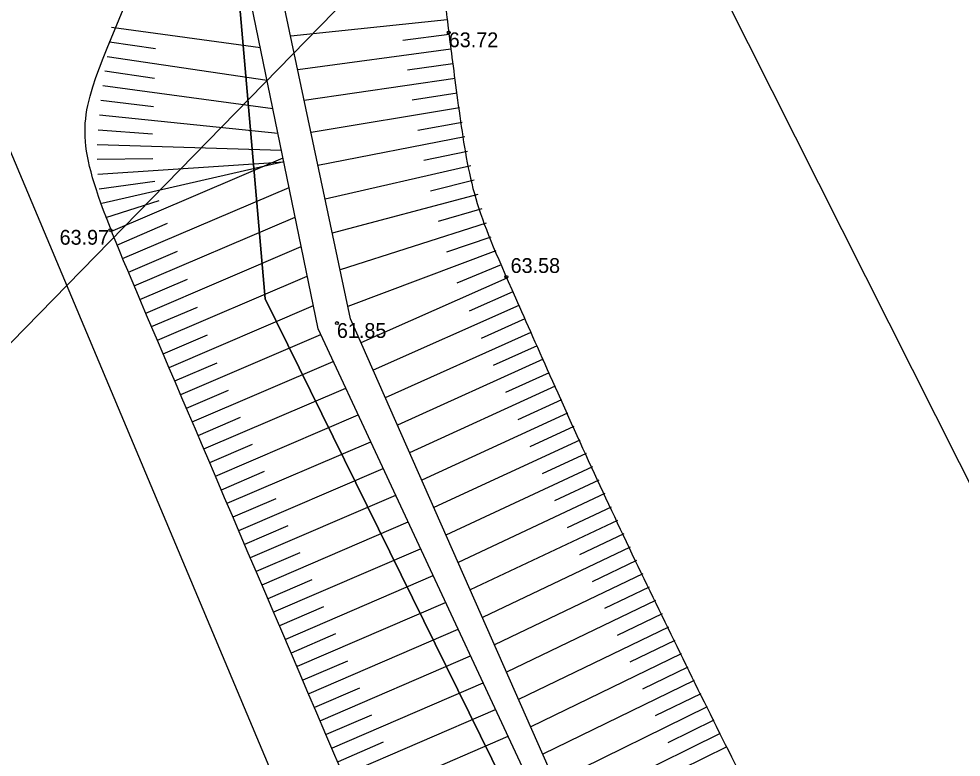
# Model space of a CAD drawing. Extents: x 616607 to 617499, y 408385 to 409695.
# Drawn here: x 617141.81 to 617173.68, y 409214.63 to 409239.59 of the extents above; entities that cross this region are included whole.
import ezdxf

# ---------------------------------------------------------------- set-up
doc = ezdxf.new("R2010")
doc.units = 0
for name, color, linetype in [('HIDG_GRAV_####_####_#', 7, 'Continuous'), ('RAMI_PLAN_####_TKST_#', 7, 'Continuous'), ('RAMI_UZMR_####_####_#', 7, 'Continuous'), ('RELJ_AATZ_####_TKST_#', 7, 'Continuous'), ('RELJ_ELEM_####_####_#', 7, 'Continuous'), ('RELJ_NOGA_####_####_#', 7, 'Continuous'), ('ROBZ_IERR_####_####_#', 7, 'Continuous'), ('ROBZ_UZMR_####_####_#', 7, 'Continuous')]:
    doc.layers.add(name, color=color, linetype=linetype)

# ---------------------------------------------------------------- blocks, each defined once
blk = doc.blocks.new('PKT')
at = {"layer": 'RELJ_ELEM_####_####_#'}
blk.add_circle((0, 0), 0.05, dxfattribs=at)

msp = doc.modelspace()

# ---------------------------------------------------------------- linework, layer by layer
at = {"layer": 'HIDG_GRAV_####_####_#'}
for points in [[(617196.049, 409072.553), (617193.886, 409072.979), (617195.921, 409087.874), (617195.921, 409087.874), (617199.518, 409112.516), (617194.569, 409134.842), (617162.019, 409207.474), (617151.93, 409229.107), (617149.428, 409241.28), (617152.359, 409253.938), (617188.564, 409303.055), (617197.968, 409312.659), (617223.456, 409346.169), (617232.567, 409363.51), (617247.671, 409422.509), (617276.576, 409461.456), (617285.007, 409472.526), (617327.765, 409527.3)], [(617198.671, 409072.074), (617200.929, 409072.435), (617202.532, 409075.622), (617201.237, 409087.874), (617202.422, 409112.516), (617197.415, 409136.544), (617162.613, 409207.758), (617153.021, 409229.447), (617150.525, 409241.262), (617153.298, 409253.658), (617189.431, 409302.264), (617198.754, 409312.12), (617224.478, 409345.652), (617234.105, 409363.027), (617250.009, 409421.44), (617285.914, 409471.848), (617328.6, 409526.531)]]:
    msp.add_lwpolyline(points, dxfattribs=at)
at = {"layer": 'RAMI_PLAN_####_TKST_#'}
msp.add_line((617357.121, 409449.318), (617128.46, 409215.262), dxfattribs=at)
at = {"layer": 'RAMI_UZMR_####_####_#'}
msp.add_lwpolyline([(617101.571, 408748.246), (617213.472, 409074.039), (617215.883, 409140.56), (617165.121, 409241.478), (617252.137, 409353.424), (617269.572, 409425.099), (617332.631, 409510.312), (617439.945, 409622.037), (617425.373, 409635.959), (617242.079, 409440.82), (617216.614, 409355.716), (617136.613, 409246.751), (617191.828, 409115.62), (617145.545, 408952.8)], dxfattribs=at)
at = {"layer": 'RELJ_NOGA_####_####_#'}
for p, q in [((617156.298, 409239.555), (617151.001, 409239.01)), ((617156.298, 409239.555), (617156.299, 409239.555)), ((617144.936, 409239.314), (617144.935, 409239.314)), ((617144.936, 409239.314), (617149.975, 409238.619)), ((617144.866, 409238.819), (617144.865, 409238.819)), ((617144.866, 409238.819), (617146.433, 409238.589)), ((617156.357, 409239.058), (617154.79, 409238.855)), ((617156.357, 409239.058), (617156.357, 409239.058)), ((617156.421, 409238.562), (617151.241, 409237.871)), ((617156.421, 409238.562), (617156.422, 409238.562)), ((617144.792, 409238.324), (617144.791, 409238.324)), ((617144.792, 409238.324), (617150.202, 409237.515)), ((617144.719, 409237.83), (617144.718, 409237.83)), ((617144.719, 409237.83), (617146.395, 409237.583)), ((617156.489, 409238.067), (617154.947, 409237.852)), ((617156.489, 409238.067), (617156.489, 409238.067)), ((617156.559, 409237.572), (617151.462, 409236.828)), ((617156.559, 409237.572), (617156.56, 409237.572)), ((617144.648, 409237.335), (617144.647, 409237.335)), ((617144.648, 409237.335), (617150.399, 409236.556)), ((617144.584, 409236.839), (617144.583, 409236.839)), ((617144.584, 409236.839), (617146.355, 409236.624)), ((617156.633, 409237.077), (617155.115, 409236.844)), ((617156.633, 409237.077), (617156.633, 409237.077)), ((617156.712, 409236.583), (617151.689, 409235.75)), ((617156.712, 409236.583), (617156.713, 409236.584)), ((617144.529, 409236.342), (617144.528, 409236.342)), ((617144.529, 409236.342), (617150.569, 409235.728)), ((617156.796, 409236.091), (617155.299, 409235.822)), ((617156.796, 409236.091), (617156.796, 409236.091)), ((617144.486, 409235.844), (617144.486, 409235.844)), ((617144.486, 409235.844), (617146.331, 409235.71)), ((617156.887, 409235.599), (617151.924, 409234.638)), ((617156.887, 409235.599), (617156.888, 409235.599)), ((617144.46, 409235.344), (617144.459, 409235.344)), ((617144.46, 409235.344), (617150.687, 409235.155)), ((617156.985, 409235.109), (617155.502, 409234.8)), ((617156.985, 409235.109), (617156.985, 409235.109)), ((617144.455, 409234.844), (617144.454, 409234.844)), ((617144.455, 409234.844), (617146.337, 409234.876)), ((617144.475, 409234.345), (617150.769, 409234.758)), ((617144.614, 409233.355), (617150.767, 409234.768)), ((617144.92, 409232.405), (617150.741, 409234.892)), ((617157.09, 409234.62), (617152.164, 409233.501)), ((617157.09, 409234.62), (617157.091, 409234.62)), ((617144.475, 409234.345), (617144.474, 409234.345)), ((617144.526, 409233.848), (617146.402, 409234.107)), ((617157.205, 409234.133), (617155.729, 409233.771)), ((617157.205, 409234.133), (617157.205, 409234.133)), ((617144.526, 409233.848), (617144.526, 409233.848)), ((617145.313, 409231.486), (617150.947, 409233.892)), ((617157.329, 409233.649), (617152.409, 409232.342)), ((617157.329, 409233.649), (617157.33, 409233.649)), ((617144.614, 409233.355), (617144.613, 409233.355)), ((617144.744, 409232.873), (617146.549, 409233.448)), ((617157.464, 409233.167), (617155.986, 409232.738)), ((617157.464, 409233.167), (617157.464, 409233.167)), ((617144.744, 409232.873), (617144.744, 409232.873)), ((617145.706, 409230.566), (617151.152, 409232.892)), ((617144.92, 409232.405), (617144.919, 409232.405)), ((617145.117, 409231.945), (617146.835, 409232.679)), ((617157.609, 409232.689), (617152.67, 409231.109)), ((617157.609, 409232.689), (617157.61, 409232.689)), ((617157.766, 409232.214), (617156.276, 409231.701)), ((617157.766, 409232.214), (617157.767, 409232.214)), ((617145.117, 409231.945), (617145.117, 409231.945)), ((617145.51, 409231.026), (617147.172, 409231.736)), ((617146.099, 409229.646), (617151.357, 409231.895)), ((617157.936, 409231.744), (617152.932, 409229.864)), ((617157.936, 409231.744), (617157.937, 409231.744)), ((617145.313, 409231.486), (617145.312, 409231.485)), ((617158.119, 409231.279), (617156.62, 409230.66)), ((617158.119, 409231.279), (617158.119, 409231.279)), ((617145.51, 409231.026), (617145.509, 409231.026)), ((617145.903, 409230.106), (617147.508, 409230.793)), ((617146.492, 409228.727), (617151.563, 409230.895)), ((617158.315, 409230.819), (617153.378, 409228.638)), ((617158.315, 409230.819), (617158.316, 409230.819)), ((617145.706, 409230.566), (617145.705, 409230.566)), ((617158.517, 409230.362), (617157.037, 409229.706)), ((617158.517, 409230.362), (617158.518, 409230.362)), ((617145.903, 409230.106), (617145.902, 409230.106)), ((617146.296, 409229.187), (617147.845, 409229.849)), ((617146.886, 409227.808), (617151.768, 409229.897)), ((617158.72, 409229.905), (617153.789, 409227.71)), ((617158.72, 409229.905), (617158.721, 409229.905)), ((617146.099, 409229.646), (617146.098, 409229.646)), ((617146.296, 409229.187), (617146.295, 409229.187)), ((617158.924, 409229.448), (617157.445, 409228.786)), ((617158.924, 409229.448), (617158.924, 409229.448)), ((617146.689, 409228.267), (617148.182, 409228.906)), ((617147.279, 409226.888), (617152.018, 409228.918)), ((617159.128, 409228.992), (617154.202, 409226.776)), ((617159.128, 409228.992), (617159.129, 409228.992)), ((617146.492, 409228.727), (617146.491, 409228.727)), ((617146.689, 409228.267), (617146.689, 409228.267)), ((617159.333, 409228.536), (617157.854, 409227.871)), ((617159.333, 409228.536), (617159.333, 409228.536)), ((617147.082, 409227.348), (617148.519, 409227.963)), ((617147.673, 409225.969), (617152.441, 409228.011)), ((617159.539, 409228.08), (617154.61, 409225.852)), ((617159.539, 409228.08), (617159.54, 409228.08)), ((617146.886, 409227.808), (617146.885, 409227.807)), ((617159.745, 409227.624), (617158.267, 409226.953)), ((617159.745, 409227.624), (617159.746, 409227.624)), ((617147.082, 409227.348), (617147.082, 409227.348)), ((617147.476, 409226.429), (617148.902, 409227.039)), ((617148.067, 409225.05), (617152.863, 409227.107)), ((617159.952, 409227.169), (617155.022, 409224.921)), ((617159.952, 409227.169), (617159.953, 409227.17)), ((617147.279, 409226.888), (617147.278, 409226.888)), ((617160.16, 409226.714), (617158.68, 409226.037)), ((617160.16, 409226.714), (617160.16, 409226.714)), ((617147.476, 409226.429), (617147.476, 409226.429)), ((617147.87, 409225.509), (617149.304, 409226.125)), ((617148.461, 409224.131), (617153.286, 409226.2)), ((617160.368, 409226.26), (617155.434, 409223.99)), ((617160.368, 409226.26), (617160.369, 409226.26)), ((617147.673, 409225.969), (617147.672, 409225.969)), ((617160.577, 409225.805), (617159.095, 409225.124)), ((617160.577, 409225.805), (617160.577, 409225.806)), ((617147.87, 409225.509), (617147.87, 409225.509)), ((617148.067, 409225.05), (617148.066, 409225.05)), ((617148.264, 409224.59), (617149.707, 409225.209)), ((617148.855, 409223.212), (617153.708, 409225.296)), ((617160.786, 409225.352), (617155.841, 409223.069)), ((617160.786, 409225.352), (617160.787, 409225.352)), ((617160.997, 409224.898), (617159.512, 409224.21)), ((617160.997, 409224.898), (617160.997, 409224.898)), ((617148.264, 409224.59), (617148.264, 409224.59)), ((617161.207, 409224.444), (617156.252, 409222.14)), ((617161.207, 409224.444), (617161.208, 409224.445)), ((617148.461, 409224.131), (617148.46, 409224.13)), ((617148.658, 409223.671), (617150.11, 409224.294)), ((617149.25, 409222.293), (617154.13, 409224.389)), ((617161.419, 409223.991), (617159.93, 409223.297)), ((617161.419, 409223.991), (617161.419, 409223.991)), ((617148.658, 409223.671), (617148.658, 409223.671)), ((617149.645, 409221.374), (617154.552, 409223.484)), ((617161.631, 409223.538), (617156.664, 409221.208)), ((617161.631, 409223.538), (617161.631, 409223.539)), ((617148.855, 409223.212), (617148.854, 409223.211)), ((617149.053, 409222.752), (617150.513, 409223.379)), ((617161.843, 409223.086), (617160.351, 409222.383)), ((617161.843, 409223.086), (617161.843, 409223.086)), ((617149.053, 409222.752), (617149.052, 409222.752)), ((617150.04, 409220.456), (617154.974, 409222.58)), ((617162.056, 409222.633), (617157.074, 409220.282)), ((617162.056, 409222.633), (617162.057, 409222.634)), ((617149.25, 409222.293), (617149.249, 409222.293)), ((617149.447, 409221.834), (617150.915, 409222.465)), ((617162.27, 409222.181), (617160.772, 409221.473)), ((617162.27, 409222.181), (617162.27, 409222.181)), ((617149.447, 409221.834), (617149.447, 409221.833)), ((617149.842, 409220.915), (617151.319, 409221.55)), ((617150.435, 409219.537), (617155.397, 409221.673)), ((617162.484, 409221.73), (617157.484, 409219.355)), ((617162.484, 409221.73), (617162.485, 409221.73)), ((617149.645, 409221.374), (617149.644, 409221.374)), ((617162.698, 409221.278), (617161.196, 409220.561)), ((617162.698, 409221.278), (617162.699, 409221.278)), ((617149.842, 409220.915), (617149.842, 409220.915)), ((617150.237, 409219.996), (617151.722, 409220.635)), ((617150.831, 409218.619), (617155.819, 409220.769)), ((617162.914, 409220.827), (617157.892, 409218.431)), ((617162.914, 409220.827), (617162.915, 409220.827)), ((617150.04, 409220.456), (617150.039, 409220.455)), ((617163.129, 409220.376), (617161.62, 409219.653)), ((617163.129, 409220.376), (617163.13, 409220.376)), ((617150.237, 409219.996), (617150.237, 409219.996)), ((617150.633, 409219.078), (617152.125, 409219.72)), ((617151.226, 409217.7), (617156.241, 409219.862)), ((617163.345, 409219.925), (617158.304, 409217.501)), ((617163.345, 409219.925), (617163.346, 409219.925)), ((617150.435, 409219.537), (617150.434, 409219.537)), ((617163.562, 409219.474), (617162.045, 409218.745)), ((617163.562, 409219.474), (617163.562, 409219.474)), ((617150.633, 409219.078), (617150.632, 409219.078)), ((617163.779, 409219.024), (617158.711, 409216.579)), ((617163.779, 409219.024), (617163.78, 409219.024)), ((617151.028, 409218.159), (617152.529, 409218.806)), ((617151.622, 409216.782), (617156.663, 409218.958)), ((617150.831, 409218.619), (617150.83, 409218.618)), ((617163.997, 409218.573), (617162.473, 409217.836)), ((617163.997, 409218.573), (617163.997, 409218.574)), ((617151.028, 409218.159), (617151.028, 409218.159)), ((617152.019, 409215.864), (617157.086, 409218.051)), ((617164.215, 409218.124), (617159.121, 409215.652)), ((617164.215, 409218.124), (617164.216, 409218.124)), ((617151.424, 409217.241), (617152.933, 409217.891)), ((617151.226, 409217.7), (617151.225, 409217.7)), ((617164.433, 409217.674), (617162.901, 409216.928)), ((617164.433, 409217.674), (617164.434, 409217.674)), ((617151.424, 409217.241), (617151.424, 409217.241)), ((617152.415, 409214.946), (617157.508, 409217.147)), ((617164.652, 409217.224), (617159.531, 409214.727)), ((617164.652, 409217.224), (617164.653, 409217.225)), ((617151.622, 409216.782), (617151.621, 409216.782)), ((617151.82, 409216.323), (617153.337, 409216.977)), ((617164.872, 409216.775), (617163.331, 409216.021)), ((617164.872, 409216.775), (617164.872, 409216.775)), ((617151.82, 409216.323), (617151.82, 409216.323)), ((617152.812, 409214.028), (617157.93, 409216.242)), ((617165.091, 409216.326), (617159.938, 409213.805)), ((617165.091, 409216.326), (617165.092, 409216.326)), ((617152.019, 409215.864), (617152.018, 409215.863)), ((617152.217, 409215.405), (617153.741, 409216.063)), ((617165.312, 409215.877), (617163.761, 409215.116)), ((617165.312, 409215.877), (617165.312, 409215.877)), ((617152.217, 409215.405), (617152.217, 409215.405)), ((617153.209, 409213.11), (617158.352, 409215.338)), ((617165.532, 409215.428), (617160.349, 409212.875)), ((617165.532, 409215.428), (617165.533, 409215.429)), ((617152.415, 409214.946), (617152.414, 409214.945)), ((617152.614, 409214.487), (617154.145, 409215.149)), ((617165.753, 409214.98), (617164.193, 409214.211)), ((617165.753, 409214.98), (617165.753, 409214.98))]:
    msp.add_line(p, q, dxfattribs=at)
for points in [[(617336.806, 409523.735), (617334.087, 409521.174), (617331.368, 409518.613), (617328.65, 409516.053), (617321.193, 409509.03), (617314.57, 409501.094), (617308.568, 409492.793), (617305.546, 409488.614), (617302.537, 409484.426), (617299.516, 409480.247), (617296.49, 409476.063), (617293.469, 409471.875), (617290.436, 409467.695), (617287.772, 409464.025), (617284.965, 409460.461), (617282.252, 409456.826), (617279.55, 409453.205), (617276.887, 409449.558), (617274.256, 409445.882), (617271.624, 409442.206), (617269.17, 409438.414), (617266.782, 409434.573), (617265.581, 409432.642), (617264.455, 409430.674), (617263.346, 409428.69), (617262.228, 409426.69), (617261.169, 409424.668), (617260.166, 409422.606), (617258.56, 409419.302), (617257.132, 409415.931), (617255.903, 409412.47), (617254.682, 409409.035), (617253.531, 409405.585), (617252.579, 409402.073), (617251.627, 409398.563), (617250.683, 409395.052), (617249.746, 409391.538), (617248.81, 409388.023), (617247.876, 409384.508), (617246.956, 409380.989), (617246.456, 409379.078), (617246.028, 409377.149), (617245.649, 409375.21), (617245.269, 409373.268), (617244.984, 409371.31), (617244.622, 409369.366), (617244.259, 409367.42), (617243.878, 409365.48), (617243.456, 409363.545), (617243.245, 409362.576), (617242.967, 409361.625), (617242.691, 409360.672), (617242.413, 409359.713), (617242.093, 409358.772), (617241.734, 409357.838), (617241.092, 409356.173), (617240.315, 409354.578), (617239.389, 409353.048), (617238.465, 409351.519), (617237.498, 409350.034), (617236.402, 409348.636), (617235.3, 409347.23), (617234.195, 409345.828), (617233.083, 409344.431), (617231.973, 409343.038), (617230.863, 409341.647), (617229.743, 409340.262), (617227.764, 409337.815), (617225.693, 409335.438), (617223.461, 409333.217), (617221.215, 409330.983), (617218.873, 409328.856), (617216.607, 409326.646), (617214.346, 409324.442), (617212.093, 409322.231), (617209.875, 409319.98), (617208.771, 409318.86), (617207.791, 409317.635), (617206.772, 409316.432), (617205.753, 409315.229), (617204.825, 409314.017), (617203.96, 409312.646), (617203.768, 409312.342), (617203.633, 409312.004), (617203.62, 409311.655), (617203.607, 409311.284), (617203.603, 409310.913), (617203.599, 409310.542), (617203.595, 409310.167), (617203.603, 409309.793), (617203.596, 409309.419), (617203.588, 409309.066), (617203.48, 409308.714), (617203.309, 409308.4), (617202.615, 409307.13), (617201.9, 409305.914), (617201.16, 409304.689), (617200.419, 409303.462), (617199.689, 409302.232), (617198.921, 409301.021), (617197.385, 409298.6), (617195.744, 409296.251), (617194.012, 409293.966), (617188.331, 409286.47), (617182.548, 409279.072), (617176.617, 409271.78), (617175.091, 409269.904), (617173.565, 409268.03), (617172.006, 409266.181), (617170.46, 409264.348), (617168.875, 409262.548), (617167.326, 409260.717), (617165.749, 409258.854), (617164.19, 409256.978), (617162.652, 409255.082), (617161.86, 409254.106), (617161.109, 409253.1), (617160.341, 409252.105), (617159.552, 409251.081), (617158.796, 409250.055), (617158.061, 409248.97), (617157.091, 409247.54), (617156.549, 409245.874), (617156.301, 409244.175), (617156.178, 409243.327), (617156.153, 409242.478), (617156.175, 409241.631), (617156.198, 409240.798), (617156.24, 409239.966), (617156.347, 409239.134), (617156.709, 409236.311), (617157.141, 409233.481), (617158.294, 409230.866), (617161.329, 409223.986), (617164.552, 409217.339), (617167.894, 409210.677), (617170.758, 409204.966), (617173.578, 409199.236), (617176.506, 409193.56), (617179.423, 409187.907), (617182.384, 409182.277), (617185.301, 409176.624), (617188.243, 409170.922), (617191.171, 409165.213), (617194.071, 409159.489), (617195.541, 409156.585), (617196.952, 409153.652), (617198.382, 409150.727), (617199.832, 409147.761), (617201.227, 409144.774), (617202.61, 409141.772), (617203.681, 409139.449), (617204.533, 409137.047), (617205.282, 409134.589), (617206.022, 409132.164), (617206.554, 409129.71), (617206.943, 409127.212), (617207.329, 409124.726), (617207.611, 409122.242), (617207.809, 409119.738), (617208.005, 409117.248), (617208.126, 409114.753), (617208.097, 409112.263), (617208.074, 409110.266), (617207.983, 409108.256), (617207.635, 409106.282), (617207.283, 409104.281), (617206.913, 409102.294), (617206.558, 409100.3), (617206.203, 409098.306), (617205.85, 409096.331), (617205.506, 409094.315), (617205.165, 409092.324), (617205.06, 409090.322), (617205.116, 409088.325), (617205.171, 409086.355), (617205.316, 409084.384), (617205.484, 409082.414), (617205.653, 409080.435), (617205.914, 409078.469), (617206.09, 409076.495), (617206.126, 409076.085), (617206.005, 409075.66), (617206.103, 409075.26)], [(617191.5, 409068.875), (617191.187, 409071.639), (617190.873, 409074.403), (617190.56, 409077.167), (617188.889, 409091.892), (617197.619, 409106.66), (617195.165, 409121.386), (617194.844, 409123.312), (617194.157, 409125.135), (617193.325, 409126.9), (617187.756, 409138.717), (617181.857, 409150.154), (617176.29, 409161.887), (617165.241, 409185.172), (617154.985, 409208.835), (617144.902, 409232.447), (617143.246, 409236.327), (617146.946, 409242.229), (617143.832, 409245.09), (617142.81, 409246.028), (617141.789, 409246.966), (617140.768, 409247.904)]]:
    msp.add_open_spline(points, degree=3, dxfattribs=at)
at = {"layer": 'ROBZ_IERR_####_####_#'}
msp.add_lwpolyline([(617119.605, 409263.967), (617148.652, 409247.272), (617150.138, 409230.13), (617196.507, 409136.07), (617200.886, 409119.423), (617196.025, 409075.262), (617232.282, 409073.757)], dxfattribs=at)
at = {"layer": 'ROBZ_UZMR_####_####_#'}
msp.add_lwpolyline([(617232.583, 409073.745), (617196.025, 409075.262), (617200.886, 409119.423), (617196.507, 409136.07), (617150.138, 409230.13), (617148.652, 409247.272), (617201.229, 409318.934), (617233.453, 409357.938), (617244.928, 409391.934), (617250.98, 409414.497), (617255.789, 409432.426), (617326.39, 409521.291), (617332.188, 409529.592), (617332.358, 409529.835), (617335.391, 409534.333), (617341.051, 409533.641), (617349.913, 409536.856), (617370.73, 409556.7), (617378.749, 409547.935), (617381.343, 409545.1)], dxfattribs=at)

# ---------------------------------------------------------------- block references
at = {"layer": 'RELJ_ELEM_####_####_#'}
for p in [(617156.347, 409239.134), (617144.902, 409232.447), (617158.294, 409230.866), (617152.564, 409229.304)]:
    msp.add_blockref('PKT', p, dxfattribs=at)

# ---------------------------------------------------------------- texts
at = {"layer": 'RELJ_AATZ_####_TKST_#'}
for s, p in [('63.72', (617156.347, 409238.634)), ('63.97', (617143.184, 409231.956)), ('63.58', (617158.44, 409231.001)), ('61.85', (617152.564, 409228.804))]:
    msp.add_text(s, height=0.5, dxfattribs=at).set_placement(p)

doc.saveas('drawing.dxf')
